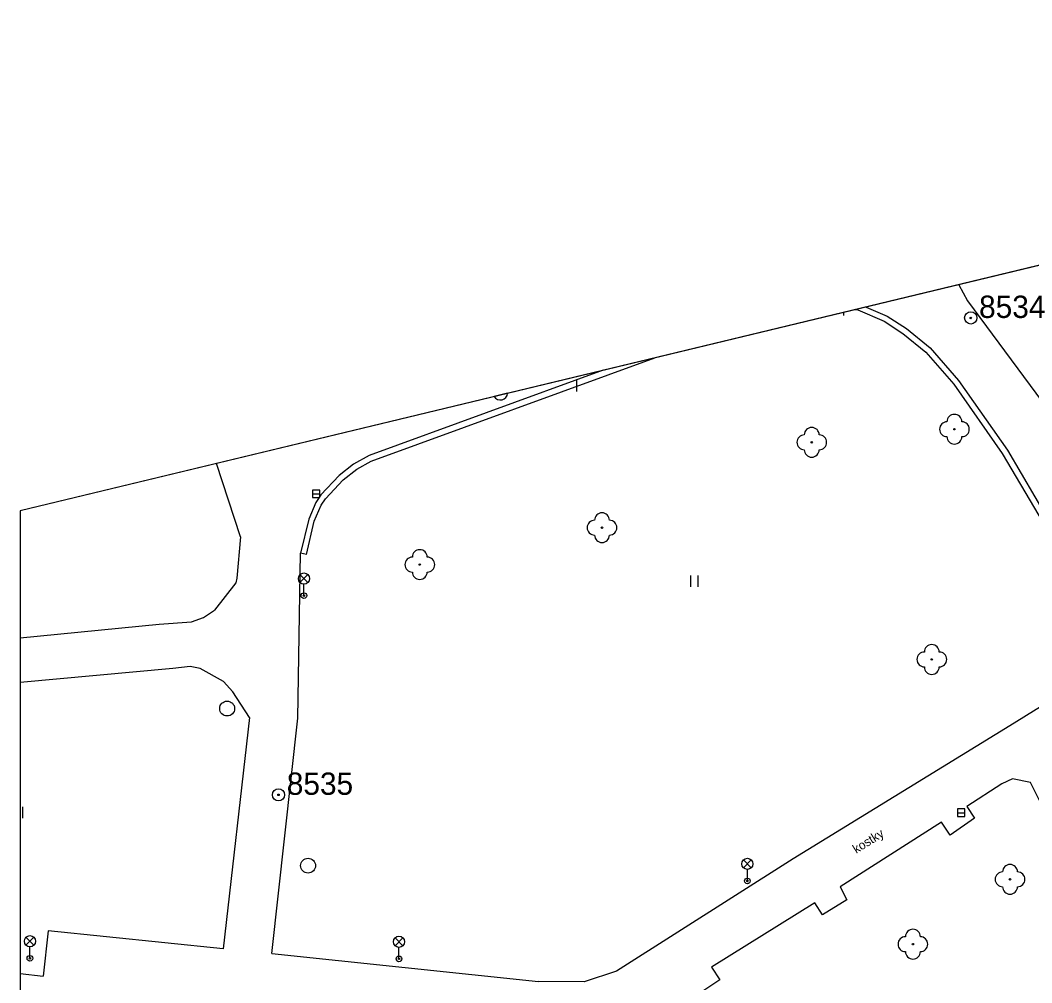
# Model space of a CAD drawing. Extents: x -492431 to -49218, y -1127123 to -112687.
# Drawn here: x -492431 to -492363, y -1126927.2 to -1126862.5 of the extents above; entities that cross this region are included whole.
import ezdxf

# ---------------------------------------------------------------- set-up
doc = ezdxf.new("R2010")
doc.units = 0
for name, color, linetype in [('Vrstva 1', 7, 'Continuous'), ('Vrstva 10', 7, 'Continuous'), ('Vrstva 22', 7, 'Continuous'), ('Vrstva 27', 7, 'Continuous'), ('Vrstva 33', 7, 'Continuous'), ('Vrstva 36', 7, 'Continuous'), ('Vrstva 40', 7, 'Continuous'), ('Vrstva 60', 7, 'Continuous'), ('Vrstva 63', 7, 'Continuous')]:
    doc.layers.add(name, color=color, linetype=linetype)

msp = doc.modelspace()

# ---------------------------------------------------------------- linework, layer by layer
at = {"layer": 'Vrstva 1'}
msp.add_line((-492313.78, -1126867.2), (-492431.031, -1126895.427), dxfattribs=at)
msp.add_lwpolyline([(-492431.031, -1126895.427), (-492431.031, -1127013.124), (-492341.24, -1127122.91)], dxfattribs=at)
at = {"layer": 'Vrstva 10'}
for p, q in [((-492367.94, -1126880.238), (-492367.35, -1126881.32)), ((-492374.893, -1126881.912), (-492374.72, -1126881.93)), ((-492367.35, -1126881.32), (-492355.72, -1126897.07)), ((-492407.43, -1126892.09), (-492388.366, -1126885.155)), ((-492391.833, -1126885.99), (-492407.57, -1126891.71)), ((-492416.22, -1126897.18), (-492417.834, -1126892.25)), ((-492411.79, -1126898.38), (-492412.18, -1126898.29)), ((-492418.7, -1126902.61), (-492417.97, -1126902.12)), ((-492421.7, -1126903.05), (-492419.52, -1126902.9)), ((-492419.52, -1126902.9), (-492418.7, -1126902.61)), ((-492420.77, -1126906.03), (-492431.031, -1126906.984)), ((-492419.61, -1126905.9), (-492420.77, -1126906.03)), ((-492418.94, -1126906.03), (-492419.61, -1126905.9)), ((-492417.37, -1126906.9), (-492418.94, -1126906.03)), ((-492416.73, -1126907.6), (-492417.37, -1126906.9)), ((-492415.62, -1126909.33), (-492416.73, -1126907.6)), ((-492415.62, -1126909.33), (-492417.38, -1126924.89)), ((-492365.04, -1126913.78), (-492367.39, -1126915.31)), ((-492364.32, -1126913.46), (-492365.04, -1126913.78)), ((-492363.12, -1126913.71), (-492364.32, -1126913.46)), ((-492362.28, -1126915.35), (-492363.12, -1126913.71)), ((-492367.39, -1126915.31), (-492366.88, -1126916.11)), ((-492369.1, -1126916.37), (-492375.92, -1126920.72)), ((-492368.52, -1126917.25), (-492369.1, -1126916.37)), ((-492366.88, -1126916.11), (-492368.52, -1126917.25)), ((-492375.92, -1126920.72), (-492375.47, -1126921.58)), ((-492377.61, -1126921.79), (-492384.57, -1126926.11)), ((-492377.1, -1126922.59), (-492377.61, -1126921.79)), ((-492375.47, -1126921.58), (-492377.1, -1126922.59)), ((-492429.16, -1126923.67), (-492429.5, -1126926.71)), ((-492417.38, -1126924.89), (-492429.16, -1126923.67)), ((-492414.11, -1126925.2), (-492396.2, -1126927.09)), ((-492384.57, -1126926.11), (-492383.99, -1126926.97)), ((-492431.031, -1126926.541), (-492429.5, -1126926.71)), ((-492383.99, -1126926.97), (-492385.69, -1126928.09))]:
    msp.add_line(p, q, dxfattribs=at)
for points in [[(-492374.72, -1126881.93), (-492372.95, -1126882.69), (-492371.7, -1126883.51), (-492370.15, -1126884.78), (-492368.28, -1126886.93), (-492365.01, -1126891.58), (-492361.33, -1126897.83), (-492359.4, -1126901.13), (-492358.84, -1126903.18), (-492358.92, -1126904.49), (-492359.11, -1126905.33), (-492359.26, -1126905.75), (-492359.62, -1126906.17)], [(-492374.163, -1126881.736), (-492372.76, -1126882.34), (-492371.46, -1126883.19), (-492369.87, -1126884.49), (-492367.96, -1126886.68), (-492364.67, -1126891.36), (-492360.99, -1126897.63), (-492359.03, -1126900.97), (-492358.44, -1126903.14), (-492358.52, -1126904.54), (-492358.72, -1126905.44), (-492358.91, -1126905.96), (-492359.32, -1126906.43)], [(-492407.57, -1126891.71), (-492408.63, -1126892.31), (-492409.6, -1126893.06), (-492410.83, -1126894.37), (-492411.15, -1126894.87), (-492411.64, -1126896), (-492412.18, -1126898.29)], [(-492411.79, -1126898.38), (-492411.26, -1126896.13), (-492410.8, -1126895.06), (-492410.51, -1126894.62), (-492409.33, -1126893.36), (-492408.41, -1126892.64), (-492407.43, -1126892.09)], [(-492416.22, -1126897.18), (-492416.46, -1126899.96), (-492416.53, -1126900.27), (-492417.97, -1126902.12)], [(-492414.11, -1126925.2), (-492412.38, -1126909.38), (-492412.18, -1126898.29)], [(-492431.031, -1126903.966), (-492421.7, -1126903.05)], [(-492359.32, -1126906.43), (-492360.38, -1126907.33), (-492364.5, -1126909.89), (-492379.07, -1126918.84), (-492390.95, -1126926.38)], [(-492390.95, -1126926.38), (-492393.13, -1126927.11), (-492396.2, -1126927.09)]]:
    msp.add_lwpolyline(points, dxfattribs=at)
at = {"layer": 'Vrstva 22'}
for centre in [(-492368.23, -1126889.95), (-492377.82, -1126890.83), (-492391.92, -1126896.57), (-492404.17, -1126899.05), (-492369.75, -1126905.43), (-492364.49, -1126920.21), (-492371.02, -1126924.57)]:
    msp.add_circle(centre, 0.05, dxfattribs=at)
for centre, start, end in [((-492368.23, -1126889.45), 360, 180), ((-492377.82, -1126890.33), 0, 180), ((-492368.73, -1126889.95), 90, 270), ((-492367.73, -1126889.95), 270, 90), ((-492378.32, -1126890.83), 90, 270), ((-492377.32, -1126890.83), 270, 90), ((-492368.23, -1126890.45), 180, 0), ((-492377.82, -1126891.33), 180, 0), ((-492392.42, -1126896.57), 90, 270), ((-492391.92, -1126896.07), 0, 180), ((-492391.42, -1126896.57), 270, 90), ((-492391.92, -1126897.07), 180, 0), ((-492404.17, -1126898.55), 0, 180), ((-492404.67, -1126899.05), 90, 270), ((-492403.67, -1126899.05), 270, 90), ((-492404.17, -1126899.55), 180, 0), ((-492370.25, -1126905.43), 90, 270), ((-492369.75, -1126904.93), 0, 180), ((-492369.25, -1126905.43), 270, 90), ((-492369.75, -1126905.93), 180, 0), ((-492364.49, -1126919.71), 360, 180), ((-492364.99, -1126920.21), 90, 270), ((-492363.99, -1126920.21), 270, 90), ((-492364.49, -1126920.71), 180, 0), ((-492371.52, -1126924.57), 90, 270), ((-492371.02, -1126924.07), 360, 180), ((-492370.52, -1126924.57), 270, 90), ((-492371.02, -1126925.07), 180, 0)]:
    msp.add_arc(centre, 0.5, start, end, dxfattribs=at)
at = {"layer": 'Vrstva 27'}
for p, q in [((-492398.263, -1126887.538), (-492399.176, -1126887.758)), ((-492411.39, -1126894.3), (-492410.89, -1126894.3)), ((-492368.02, -1126915.73), (-492367.52, -1126915.73))]:
    msp.add_line(p, q, dxfattribs=at)
for points in [[(-492411.39, -1126894.55), (-492410.89, -1126894.55), (-492410.89, -1126894.05), (-492411.39, -1126894.05)], [(-492368.02, -1126915.98), (-492367.52, -1126915.98), (-492367.52, -1126915.48), (-492368.02, -1126915.48)]]:
    msp.add_lwpolyline(points, close=True, dxfattribs=at)
for centre in [(-492417.12, -1126908.73), (-492411.68, -1126919.29)]:
    msp.add_circle(centre, 0.5, dxfattribs=at)
msp.add_arc((-492398.76, -1126887.48), 0.5, 213.7608, 353.31046, dxfattribs=at)
at = {"layer": 'Vrstva 33'}
for p, q in [((-492375.66, -1126882.3), (-492375.66, -1126882.097)), ((-492393.62, -1126887.42), (-492393.62, -1126886.645)), ((-492412.225, -1126899.725), (-492411.695, -1126900.255)), ((-492412.225, -1126900.255), (-492411.695, -1126899.725)), ((-492411.96, -1126901.14), (-492411.96, -1126900.365)), ((-492382.415, -1126918.905), (-492381.885, -1126919.435)), ((-492382.415, -1126919.435), (-492381.885, -1126918.905)), ((-492382.15, -1126920.32), (-492382.15, -1126919.545)), ((-492430.645, -1126924.105), (-492430.115, -1126924.635)), ((-492430.645, -1126924.635), (-492430.115, -1126924.105)), ((-492430.38, -1126925.52), (-492430.38, -1126924.745)), ((-492405.835, -1126924.145), (-492405.305, -1126924.675)), ((-492405.835, -1126924.675), (-492405.305, -1126924.145)), ((-492405.57, -1126925.56), (-492405.57, -1126924.785))]:
    msp.add_line(p, q, dxfattribs=at)
for centre, radius in [((-492411.96, -1126899.99), 0.375), ((-492411.96, -1126901.14), 0.19), ((-492411.96, -1126901.14), 0.05), ((-492382.15, -1126919.17), 0.375), ((-492382.15, -1126920.32), 0.19), ((-492382.15, -1126920.32), 0.05), ((-492430.38, -1126924.37), 0.375), ((-492405.57, -1126924.41), 0.375), ((-492430.38, -1126925.52), 0.19), ((-492430.38, -1126925.52), 0.05), ((-492405.57, -1126925.56), 0.19), ((-492405.57, -1126925.56), 0.05)]:
    msp.add_circle(centre, radius, dxfattribs=at)
at = {"layer": 'Vrstva 36'}
for p, q in [((-492385.95, -1126900.54), (-492385.95, -1126899.79)), ((-492385.45, -1126900.54), (-492385.45, -1126899.79)), ((-492430.85, -1126916.09), (-492430.85, -1126915.34))]:
    msp.add_line(p, q, dxfattribs=at)
at = {"layer": 'Vrstva 60'}
msp.add_lwpolyline([(-492166.731, -1127000), (-492133.025, -1126976.26), (-492272.695, -1126862.455), (-492313.78, -1126867.2), (-492431.031, -1126895.427), (-492431.031, -1127000)], dxfattribs=at)
at = {"layer": 'Vrstva 63'}
for centre, radius in [((-492367.13, -1126882.47), 0.412), ((-492367.13, -1126882.47), 0.05), ((-492413.67, -1126914.53), 0.412), ((-492413.67, -1126914.53), 0.05)]:
    msp.add_circle(centre, radius, dxfattribs=at)

# ---------------------------------------------------------------- texts
at = {"layer": 'Vrstva 40'}
msp.add_text('kostky', height=0.6, rotation=32.21362, dxfattribs=at).set_placement((-492374.829, -1126918.499))
at = {"layer": 'Vrstva 63'}
for s, p in [(' 8534', (-492367.13, -1126882.47)), (' 8535', (-492413.67, -1126914.53))]:
    msp.add_text(s, height=1.5, dxfattribs=at).set_placement(p)

doc.saveas('drawing.dxf')
